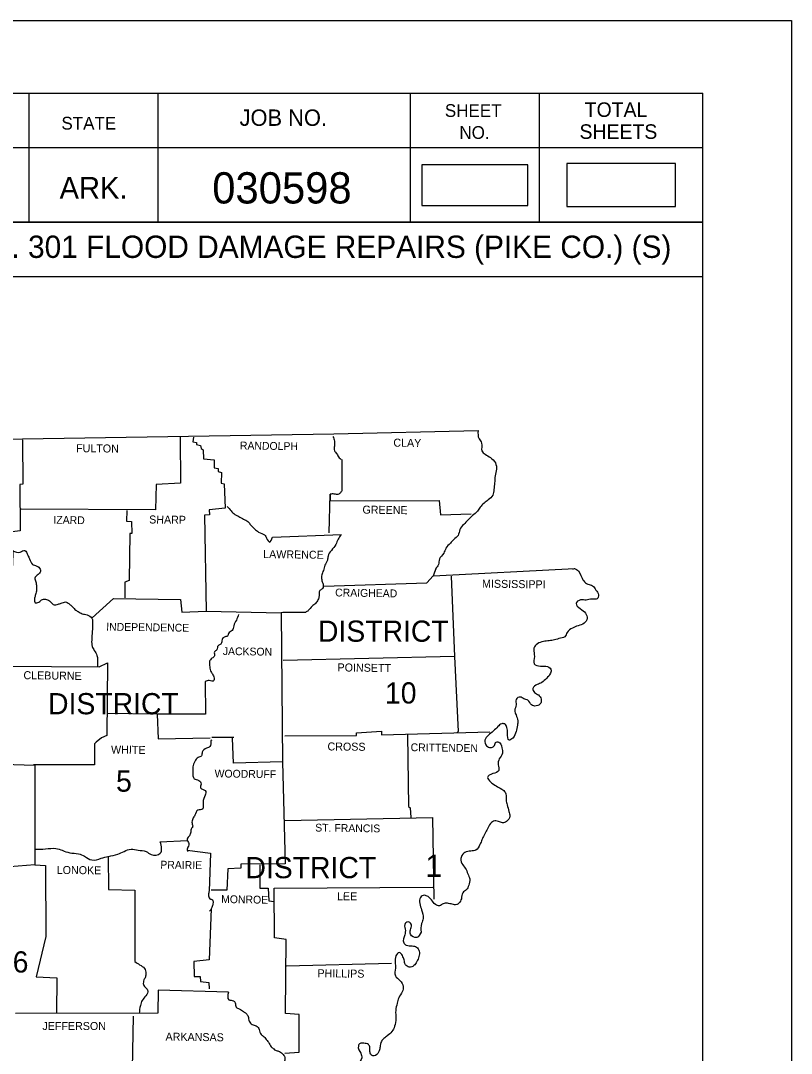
# Model space of a CAD drawing. Extents: x 79818 to 83933, y 50884 to 53307.
# Drawn here: x 83518 to 83933, y 52752 to 53307 of the extents above; entities that cross this region are included whole.
import ezdxf

# ---------------------------------------------------------------- set-up
doc = ezdxf.new("R2010")
doc.units = 0
for name, color, linetype in [('Default', 7, 'Continuous'), ('R_Border', 7, 'Continuous'), ('R_Border Notes', 7, 'Continuous'), ('R_No Plot', 7, 'Continuous')]:
    doc.layers.add(name, color=color, linetype=linetype)

msp = doc.modelspace()

# ---------------------------------------------------------------- linework, layer by layer
at = {"layer": 'Default'}
for p, q in [((83740.47, 53008.98), (83741.67, 53012.68)), ((83740.77, 53010.18), (83741.97, 53013.08)), ((83621.27, 52922.38), (83633.17, 52922.38))]:
    msp.add_line(p, q, dxfattribs=at)
for points in [[(83734.13, 53208.19), (83791.27, 53208.19), (83791.27, 53230.05), (83734.13, 53230.05)], [(83812.23, 53207.57), (83870.57, 53207.57), (83870.57, 53230.67), (83812.23, 53230.67)]]:
    msp.add_lwpolyline(points, close=True, dxfattribs=at)
for points in [[(83215.87, 53082.48), (83377.57, 53082.38), (83519.47, 53082.68), (83686.87, 53085.28), (83764.47, 53087.08)], [(83519.47, 53082.08), (83519.67, 53058.28), (83517.97, 53058.18), (83518.27, 53033.28), (83511.27, 53032.28), (83511.87, 53025.58), (83514.27, 53022.48), (83514.07, 53014.58), (83500.47, 53014.08), (83499.97, 53001.88), (83487.57, 53001.48), (83486.97, 52986.68), (83487.67, 52985.48), (83487.97, 52961.88), (83509.37, 52960.48), (83509.07, 52907.78), (83526.07, 52907.28), (83526.07, 52853.68), (83512.67, 52852.68), (83511.67, 52840.88), (83489.17, 52840.78)], [(83604.17, 53083.58), (83604.37, 53058.78), (83591.37, 53058.08), (83590.97, 53044.48), (83518.67, 53044.88)], [(83611.37, 53083.48), (83611.07, 53081.08), (83613.07, 53080.78), (83612.97, 53079.58), (83615.27, 53079.08), (83615.47, 53077.48), (83616.57, 53076.78), (83616.87, 53071.98), (83622.57, 53071.38), (83622.57, 53067.08), (83624.67, 53066.78), (83624.67, 53065.08), (83626.47, 53064.58), (83626.37, 53058.78), (83627.97, 53058.48), (83628.37, 53045.38), (83619.87, 53044.58), (83619.97, 53041.78), (83617.37, 53041.68), (83618.27, 52990.08), (83658.57, 52989.18), (83659.27, 52908.98), (83632.97, 52908.28), (83632.47, 52921.78)], [(83691.27, 53071.48), (83691.27, 53054.58)], [(83684.47, 53032.08), (83684.97, 53052.98), (83684.97, 53049.28), (83743.47, 53049.58), (83744.27, 53041.78), (83760.77, 53042.38)], [(83575.57, 53044.18), (83575.37, 53038.38), (83578.17, 53038.18), (83578.27, 53031.78), (83577.27, 53031.78), (83576.87, 53006.58), (83574.57, 53005.58), (83574.57, 52997.18)], [(83653.87, 53029.88), (83690.97, 53031.18)], [(83740.47, 53008.98), (83816.37, 53012.88)], [(83681.47, 53003.48), (83736.97, 53005.28), (83740.27, 53009.08)], [(83750.07, 53008.88), (83751.77, 52965.58), (83753.77, 52925.28)], [(83556.97, 52986.48), (83568.37, 52996.78), (83604.37, 52996.28), (83605.07, 52989.58), (83618.17, 52990.08)], [(83671.67, 52989.38), (83659.47, 52989.38), (83658.57, 52989.18)], [(83751.77, 52965.58), (83659.67, 52963.48)], [(83509.37, 52960.48), (83560.77, 52960.18), (83565.17, 52962.28), (83564.87, 52923.18), (83561.87, 52921.88), (83559.17, 52919.58), (83558.27, 52918.68), (83558.17, 52907.48), (83525.47, 52907.48)], [(83617.77, 52952.28), (83617.97, 52934.68), (83591.97, 52934.58), (83565.27, 52935.08)], [(83591.97, 52934.58), (83592.37, 52921.48), (83620.47, 52921.98)], [(83660.47, 52922.98), (83699.07, 52923.18), (83699.17, 52924.58), (83712.57, 52925.58), (83712.57, 52923.48), (83770.77, 52925.08)], [(83726.57, 52923.48), (83727.07, 52884.98), (83727.97, 52884.38), (83728.27, 52879.18)], [(83726.57, 52923.48), (83727.07, 52884.98), (83727.97, 52884.38), (83728.27, 52879.18)], [(83726.57, 52923.48), (83727.07, 52884.98), (83727.97, 52884.38), (83728.27, 52879.18)], [(83726.57, 52923.48), (83727.07, 52884.98), (83727.97, 52884.38), (83728.27, 52879.18)], [(83726.57, 52923.48), (83727.07, 52884.98), (83727.97, 52884.38), (83728.27, 52879.18)], [(83753.07, 52924.58), (83753.77, 52925.28)], [(83621.27, 52920.68), (83620.77, 52920.58)], [(83659.27, 52908.98), (83660.77, 52854.18), (83636.97, 52854.08), (83636.87, 52851.88), (83629.97, 52851.48), (83629.37, 52840.08), (83620.97, 52840.08)], [(83660.47, 52877.48), (83739.87, 52879.08)], [(83739.87, 52879.08), (83740.67, 52835.28)], [(83739.87, 52879.08), (83740.67, 52835.28)], [(83739.87, 52879.08), (83740.67, 52835.28)], [(83739.87, 52879.08), (83740.67, 52835.28)], [(83739.87, 52879.08), (83740.67, 52835.28)], [(83739.87, 52879.08), (83740.67, 52835.28)], [(83739.87, 52879.08), (83740.67, 52835.28)], [(83739.87, 52879.08), (83740.67, 52835.28)], [(83593.57, 52866.08), (83608.07, 52866.78)], [(83608.07, 52861.58), (83620.57, 52859.98), (83619.87, 52839.58)], [(83565.57, 52858.28), (83565.77, 52840.38), (83579.87, 52840.08), (83579.97, 52801.68)], [(83526.07, 52853.68), (83531.87, 52853.28), (83531.97, 52815.08), (83526.77, 52793.38), (83537.87, 52792.88), (83537.77, 52773.77)], [(83647.17, 52853.58), (83647.07, 52841.18), (83651.67, 52841.18), (83651.87, 52834.28), (83654.77, 52833.98)], [(83660.47, 52752.48), (83668.27, 52752.98), (83668.17, 52773.28), (83660.87, 52773.78), (83661.27, 52813.48), (83654.97, 52814.38), (83654.77, 52841.08), (83740.07, 52841.68)], [(83620.97, 52829.98), (83619.77, 52802.58), (83611.57, 52801.68), (83611.77, 52793.58), (83615.07, 52793.68), (83615.17, 52790.88), (83619.67, 52790.38), (83619.77, 52787.08)], [(83661.47, 52799.38), (83717.87, 52800.78)], [(83630.17, 52785.28), (83592.37, 52786.28), (83592.17, 52773.98), (83515.68, 52773.68)], [(83579.07, 52772.38), (83578.27, 52734.68), (83592.17, 52733.58)]]:
    msp.add_lwpolyline(points, dxfattribs=at)
for points in [[(83686.37, 53083.98), (83687.27, 53081.48), (83687.17, 53078.78), (83687.17, 53076.28), (83688.47, 53074.58), (83689.77, 53072.48), (83690.77, 53071.58)], [(83764.47, 53087.08), (83764.97, 53082.68), (83766.37, 53080.38), (83766.57, 53076.18), (83768.27, 53074.38), (83771.17, 53072.58), (83773.77, 53069.68), (83774.37, 53066.28), (83773.57, 53062.78), (83773.37, 53058.88), (83772.97, 53055.48), (83772.37, 53052.38), (83769.97, 53049.88), (83767.67, 53048.08), (83765.57, 53045.98), (83764.07, 53043.78), (83761.47, 53041.38), (83758.87, 53038.88), (83756.77, 53036.68), (83754.67, 53033.88), (83753.67, 53030.78), (83751.37, 53028.58), (83749.57, 53026.58), (83747.17, 53023.88), (83745.97, 53021.18), (83743.67, 53018.08), (83743.17, 53015.08), (83741.67, 53012.68), (83741.57, 53012.28)], [(83690.87, 53054.28), (83689.57, 53052.98), (83687.07, 53052.98), (83684.97, 53052.98)], [(83629.47, 53046.28), (83631.67, 53043.98), (83633.57, 53042.08), (83635.77, 53040.98), (83638.37, 53039.48), (83640.67, 53038.28), (83642.17, 53036.38), (83644.27, 53034.28), (83646.37, 53032.58), (83649.67, 53030.98), (83650.77, 53029.28), (83652.27, 53027.18), (83653.87, 53029.88)], [(83690.67, 53031.08), (83689.17, 53028.68), (83687.97, 53025.88), (83685.57, 53022.68), (83683.77, 53019.58), (83683.47, 53017.48), (83682.07, 53014.68), (83681.27, 53011.88), (83680.37, 53009.48), (83680.37, 53006.98), (83681.07, 53004.48), (83680.87, 53002.18), (83679.37, 53001.08), (83678.97, 52998.18), (83678.37, 52996.18), (83677.07, 52994.18), (83675.17, 52992.68), (83673.17, 52990.38), (83671.67, 52989.38)], [(83514.27, 53022.48), (83518.27, 53021.78), (83520.67, 53022.68), (83522.37, 53020.08), (83523.27, 53018.08), (83524.77, 53015.18), (83527.17, 53014.28), (83528.97, 53012.68), (83528.97, 53010.98), (83527.37, 53009.38), (83526.17, 53007.78), (83526.57, 53005.88), (83526.97, 53003.28), (83526.97, 53000.78), (83526.37, 52998.48), (83525.87, 52996.38), (83526.37, 52994.58), (83528.27, 52994.88), (83530.27, 52996.38), (83532.37, 52996.38), (83534.37, 52995.28), (83536.47, 52993.38), (83538.57, 52993.78), (83540.27, 52994.28), (83542.67, 52994.98), (83544.37, 52994.08), (83545.87, 52992.88), (83547.67, 52990.98), (83549.37, 52989.78), (83551.57, 52988.68), (83554.27, 52987.98), (83556.77, 52986.28), (83557.17, 52983.38), (83557.07, 52980.88), (83556.87, 52977.78), (83556.67, 52974.38), (83556.97, 52971.08), (83558.07, 52968.88), (83559.47, 52966.28), (83559.87, 52963.88), (83559.77, 52960.08)], [(83815.27, 53012.78), (83816.37, 53012.88), (83819.77, 53009.28), (83821.27, 53006.28), (83823.47, 53004.58), (83825.97, 53003.68), (83827.87, 53001.38), (83829.17, 52998.88), (83828.47, 52996.68), (83825.67, 52996.48), (83822.57, 52995.98), (83819.57, 52996.08), (83817.17, 52994.08), (83819.37, 52991.38), (83822.27, 52988.88), (83823.07, 52986.18), (83821.47, 52983.58), (83818.27, 52982.18), (83815.17, 52980.98), (83812.37, 52978.58), (83811.07, 52976.28), (83807.97, 52975.28), (83804.77, 52974.38), (83801.97, 52974.08), (83798.77, 52973.48), (83795.67, 52971.98), (83794.37, 52969.38), (83794.77, 52965.68), (83794.67, 52961.78), (83797.97, 52960.48), (83800.87, 52960.38), (83803.67, 52958.88), (83803.37, 52956.68), (83801.27, 52953.88), (83798.77, 52951.68), (83796.27, 52950.58), (83793.97, 52948.48), (83794.77, 52946.38), (83796.87, 52944.98), (83798.37, 52942.68), (83798.17, 52940.58), (83795.77, 52939.08), (83793.17, 52939.68), (83791.27, 52942.18), (83789.07, 52942.98), (83787.17, 52943.88), (83784.97, 52942.58), (83784.97, 52939.68), (83784.17, 52936.58), (83784.87, 52934.28), (83785.77, 52931.08), (83785.67, 52928.68), (83784.87, 52925.28), (83783.17, 52921.78), (83781.17, 52920.68), (83780.37, 52924.48), (83779.97, 52927.58), (83778.77, 52929.38), (83777.17, 52929.48), (83775.07, 52927.98), (83772.77, 52925.68), (83769.87, 52923.18), (83768.17, 52920.68), (83769.07, 52917.58), (83771.27, 52916.78), (83772.97, 52917.38), (83773.87, 52919.38), (83775.57, 52919.68), (83777.17, 52916.58)], [(83635.67, 52988.28), (83634.47, 52985.18), (83633.07, 52982.18), (83632.17, 52979.58), (83630.27, 52978.08), (83629.67, 52976.68), (83627.97, 52976.08), (83626.67, 52974.08), (83626.07, 52972.28), (83624.67, 52971.48), (83623.97, 52969.28), (83622.67, 52968.08), (83622.77, 52966.08), (83621.27, 52964.68), (83620.07, 52963.08), (83620.07, 52960.88), (83620.57, 52957.98), (83621.57, 52956.28), (83622.47, 52954.08), (83622.37, 52952.68), (83619.87, 52952.68), (83617.77, 52952.28)], [(83620.77, 52920.58), (83620.27, 52917.28), (83618.37, 52916.38), (83616.17, 52914.18), (83615.67, 52912.18), (83613.87, 52911.38), (83612.17, 52909.28), (83611.07, 52906.38), (83611.07, 52903.38), (83611.77, 52899.98), (83614.27, 52899.08), (83615.47, 52897.08), (83615.27, 52894.98), (83617.67, 52893.58), (83618.07, 52892.38), (83617.67, 52891.08), (83616.57, 52887.38), (83616.67, 52884.88), (83616.47, 52883.78), (83613.77, 52883.08), (83612.17, 52880.38), (83611.07, 52878.48), (83610.67, 52875.98), (83610.97, 52874.18), (83610.17, 52872.78), (83609.87, 52870.68), (83608.87, 52868.88), (83607.97, 52867.18), (83608.97, 52865.18), (83608.67, 52863.78), (83608.07, 52861.58), (83608.57, 52860.88)], [(83777.17, 52916.58), (83777.57, 52913.68), (83775.87, 52910.58), (83775.27, 52907.48), (83775.57, 52904.38), (83772.37, 52902.68), (83769.57, 52900.68), (83771.17, 52898.28), (83774.17, 52896.08), (83777.17, 52894.38), (83779.07, 52892.68), (83779.57, 52888.58), (83780.07, 52885.98), (83781.07, 52882.38), (83781.47, 52879.88), (83779.67, 52876.88), (83777.57, 52876.28), (83775.37, 52876.98), (83772.77, 52877.18), (83770.67, 52875.18), (83769.17, 52872.38), (83767.67, 52869.58), (83766.57, 52867.18), (83765.47, 52864.58), (83763.27, 52861.58), (83760.57, 52861.08), (83757.37, 52860.28), (83755.47, 52858.08), (83755.77, 52854.38), (83757.57, 52851.88), (83758.97, 52848.78), (83759.97, 52846.08), (83759.47, 52842.68), (83758.07, 52840.18), (83756.27, 52838.68), (83755.47, 52835.48), (83754.17, 52833.08), (83752.97, 52832.28), (83750.57, 52832.48), (83747.97, 52832.98), (83745.77, 52832.78), (83743.67, 52831.68), (83741.57, 52832.38), (83739.37, 52834.78), (83737.57, 52836.58), (83735.57, 52837.28), (83733.47, 52836.18), (83733.07, 52832.88), (83734.07, 52829.48), (83734.97, 52824.88), (83734.07, 52822.08), (83733.77, 52817.48)], [(83526.07, 52862.07), (83531.87, 52862.28), (83537.37, 52862.48), (83540.87, 52861.48), (83544.87, 52860.18), (83549.57, 52859.58), (83552.87, 52858.28), (83556.77, 52856.28), (83561.77, 52857.18), (83565.67, 52858.18), (83570.77, 52859.48), (83574.07, 52860.88), (83577.87, 52862.08), (83581.67, 52861.58), (83585.97, 52860.78), (83588.67, 52859.18), (83593.57, 52859.88), (83593.57, 52866.08)], [(83619.87, 52839.58), (83619.47, 52837.58), (83620.27, 52835.48), (83621.67, 52834.78), (83621.87, 52832.78), (83621.37, 52830.78), (83620.97, 52829.98), (83620.07, 52828.78)], [(83733.77, 52817.48), (83731.47, 52814.58), (83728.07, 52816.38), (83728.07, 52818.78), (83728.57, 52821.28), (83727.37, 52822.88), (83725.27, 52822.18), (83725.27, 52819.08), (83725.07, 52816.08), (83724.47, 52811.78), (83725.87, 52810.48), (83729.07, 52810.08), (83731.37, 52809.48), (83732.77, 52807.18), (83732.67, 52804.38), (83731.57, 52801.68), (83729.97, 52799.48), (83727.47, 52798.68), (83725.47, 52799.98), (83724.67, 52802.58), (83723.77, 52804.88), (83722.07, 52806.58), (83720.27, 52804.68), (83719.87, 52801.18), (83719.97, 52798.18), (83719.97, 52794.08), (83722.57, 52791.38), (83724.17, 52788.28), (83723.67, 52785.48), (83721.77, 52782.18), (83720.97, 52779.28), (83720.17, 52775.38), (83720.27, 52771.08), (83719.57, 52766.88), (83718.17, 52764.08), (83715.57, 52761.78), (83713.87, 52760.28), (83712.47, 52758.78), (83711.77, 52755.78), (83711.27, 52753.68), (83709.37, 52751.18), (83707.87, 52750.98), (83706.67, 52751.98), (83706.27, 52753.68), (83706.27, 52755.38), (83705.47, 52757.08), (83702.97, 52757.78), (83700.97, 52757.68), (83700.07, 52756.28), (83701.37, 52752.38), (83701.87, 52749.88), (83701.17, 52746.48), (83701.57, 52746.08), (83697.97, 52744.18), (83695.07, 52743.88), (83692.67, 52743.18), (83690.37, 52741.68), (83689.27, 52739.48), (83687.67, 52737.68), (83686.27, 52735.98), (83684.37, 52735.18), (83682.27, 52735.58), (83679.47, 52735.88), (83677.87, 52733.88), (83678.37, 52730.98), (83680.27, 52729.28), (83683.07, 52728.48), (83685.97, 52728.68), (83688.77, 52728.98), (83691.37, 52727.58), (83690.87, 52724.88), (83688.37, 52723.58), (83684.67, 52723.18), (83681.67, 52723.48), (83678.07, 52722.68), (83676.27, 52720.38), (83677.27, 52716.88), (83681.17, 52715.48), (83682.97, 52712.18), (83683.07, 52709.08), (83681.77, 52704.98), (83679.97, 52703.08), (83676.47, 52702.28), (83673.77, 52701.78), (83673.37, 52697.18), (83672.17, 52694.88), (83670.07, 52694.18), (83667.07, 52695.68), (83665.27, 52696.38), (83663.07, 52697.38), (83660.27, 52699.08), (83658.17, 52698.78), (83658.77, 52694.38), (83658.97, 52694.18), (83661.37, 52690.88), (83663.77, 52688.28), (83664.87, 52685.18)], [(83579.97, 52801.68), (83582.47, 52799.98), (83585.07, 52797.98), (83585.77, 52795.28), (83585.57, 52793.38), (83584.77, 52791.78), (83584.57, 52789.28), (83585.77, 52787.48), (83586.87, 52785.98), (83585.77, 52783.28), (83583.87, 52780.78), (83582.87, 52777.98), (83582.17, 52773.78)], [(83630.17, 52785.28), (83630.47, 52781.18), (83632.87, 52780.58), (83633.87, 52779.48), (83634.37, 52777.18), (83636.07, 52776.18), (83638.37, 52774.78), (83639.77, 52773.78), (83640.77, 52772.18), (83641.37, 52769.58), (83642.97, 52767.88), (83645.17, 52767.08), (83646.77, 52765.18), (83647.77, 52762.48), (83649.37, 52761.28), (83650.97, 52759.18), (83651.77, 52758.28), (83653.17, 52755.88), (83654.57, 52754.68), (83655.57, 52753.98), (83657.17, 52753.48), (83659.17, 52752.18), (83660.47, 52750.18), (83660.47, 52748.68), (83659.97, 52746.38), (83659.57, 52743.98), (83659.37, 52741.28), (83659.17, 52738.88), (83660.07, 52736.88), (83659.57, 52733.88), (83658.57, 52732.28), (83658.47, 52730.08), (83658.17, 52726.78), (83657.77, 52724.88), (83656.87, 52721.78), (83655.57, 52720.18)]]:
    msp.add_spline(points, degree=3, dxfattribs=at)
at = {"layer": 'R_Border'}
for p, q in [((80723.6, 53268.52), (83885.4, 53268.52)), ((83522.8, 53268.52), (83522.8, 53199.12)), ((83592.2, 53268.52), (83592.2, 53199.12)), ((83728, 53268.52), (83728, 53199.12)), ((83797.4, 53268.52), (83797.4, 53199.12)), ((83885.4, 51213.92), (83885.4, 53268.52)), ((83885.4, 53239.12), (83454.4, 53239.12)), ((83885.4, 53239.32), (83885.4, 53239.32)), ((83885.4, 53199.12), (83454.4, 53199.12)), ((83484, 53199.12), (83885.4, 53199.12)), ((83885.4, 53169.72), (83259, 53169.72))]:
    msp.add_line(p, q, dxfattribs=at)
at = {"layer": 'R_No Plot'}
msp.add_line((80599.59, 53307.47), (83932.93, 53307.47), dxfattribs=at)
msp.add_lwpolyline([(80599.53, 53307.47), (83932.93, 53307.47), (83932.93, 51174.09), (80599.53, 51174.09)], close=True, dxfattribs=at)

# ---------------------------------------------------------------- texts
at = {"layer": 'Default'}
for s, height, rotation, p in [('CLAY', 4.299, 359.2258, (83718.87, 53078.48)), ('FULTON', 4.3, 359.4996, (83548.27, 53075.48)), ('RANDOLPH', 4.201, 359.2583, (83636.37, 53076.98)), ('GREENE', 4.301, 359.2361, (83702.27, 53042.48)), ('IZARD', 4.199, 358.9258, (83536.07, 53037.08)), ('SHARP', 4.3, 359.3905, (83587.57, 53037.18)), ('LAWRENCE', 4.301, 359.2678, (83648.87, 53018.58)), ('MISSISSIPPI', 4.2995, 359.3097, (83766.57, 53002.68)), ('CRAIGHEAD', 4.201, 359.1159, (83687.57, 52997.98)), ('INDEPENDENCE', 4.1993, 359.2187, (83564.47, 52979.58)), ('JACKSON', 4.199, 359.1352, (83627.17, 52966.48)), ('POINSETT', 4.3, 359.1987, (83688.87, 52957.68)), ('CLEBURNE', 4.3, 359.2535, (83519.97, 52953.48)), ('WHITE', 4.301, 359.3139, (83567.07, 52913.48)), ('CROSS', 4.3, 359.3839, (83683.47, 52915.18)), ('CRITTENDEN', 4.201, 359.213, (83728.17, 52914.78)), ('WOODRUFF', 4.199, 359.2748, (83622.77, 52900.68)), ('ST. FRANCIS', 4.1993, 359.2216, (83676.87, 52871.58)), ('PRAIRIE', 4.2, 359.2116, (83593.57, 52851.68)), ('LONOKE', 4.301, 359.4974, (83537.87, 52848.78)), ('LEE', 4.301, 359.4327, (83688.57, 52834.68)), ('MONROE', 4.199, 359.0331, (83626.27, 52833.18)), ('PHILLIPS', 4.3, 359.3179, (83678.07, 52793.28)), ('ARKANSAS', 4.3, 359.2678, (83596.37, 52759.2))]:
    msp.add_text(s, height=height, rotation=rotation, dxfattribs=at).set_placement(p)
for s, height, p in [('DISTRICT', 11.4, (83678.37, 52973.58)), ('10', 11.4, (83714.4, 52940.38)), ('DISTRICT', 11.4, (83533.23, 52934.59)), ('5', 11.4, (83569.77, 52892.98)), ('DISTRICT', 11.4, (83639.37, 52846.48)), ('1', 12, (83736.17, 52847.18)), ('DISTRICT 6', 11.4, (83439.67, 52795.78)), ('JEFFERSON', 4.3, (83530.17, 52764.88))]:
    msp.add_text(s, height=height, dxfattribs=at).set_placement(p)
at = {"layer": 'R_Border'}
for s, height, p in [('JOB NO.', 8.792, (83636.2, 53250.92)), ('SHEET', 6.84, (83746.6, 53255.72)), ('TOTAL', 7.819, (83821.8, 53255.72)), ('STATE', 6.84, (83540.4, 53248.92)), ('NO.', 6.84, (83754.4, 53243.92)), ('SHEETS', 7.819, (83819, 53243.92)), ('ARK.', 11.723, (83539.4, 53211.72))]:
    msp.add_text(s, height=height, dxfattribs=at).set_placement(p)
at = {"layer": 'R_Border Notes'}
for s, height, p in [('030598', 16.8, (83621.51, 53209.18)), ('HWY. 301 FLOOD DAMAGE REPAIRS (PIKE CO.) (S)', 12, (83476.09, 53179.92))]:
    msp.add_text(s, height=height, dxfattribs=at).set_placement(p)

doc.saveas('drawing.dxf')
